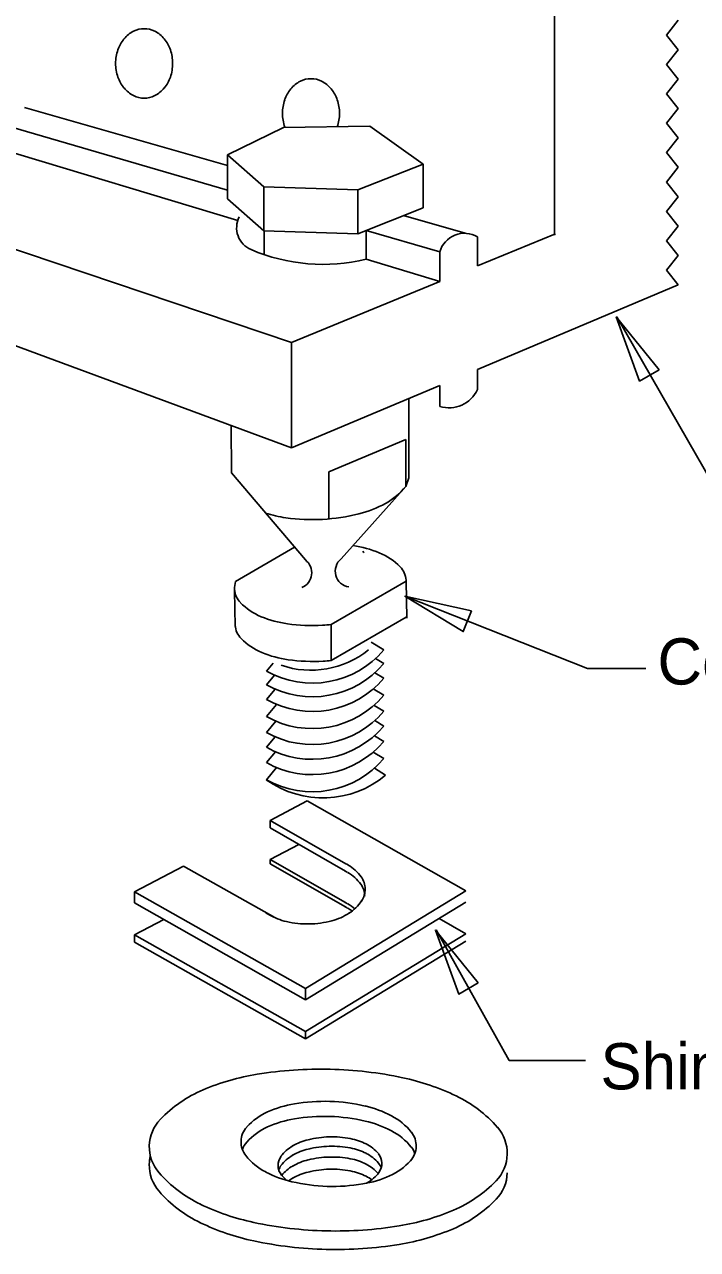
# Model space of a CAD drawing. Extents: x 12.3 to 19.6, y 5.9 to 16.2.
# Drawn here: x 16.612 to 17.486, y 8.113 to 9.704 of the extents above; entities that cross this region are included whole.
import ezdxf

# ---------------------------------------------------------------- set-up
doc = ezdxf.new("R2010")
doc.units = 0
for name, color, linetype in [('DETL-DIMS', 7, 'Continuous'), ('DETL-LINE', 7, 'Continuous'), ('DETL-NOTE', 7, 'Continuous')]:
    doc.layers.add(name, color=color, linetype=linetype)

msp = doc.modelspace()

# ---------------------------------------------------------------- linework, layer by layer
at = {"layer": 'DETL-DIMS'}
for p, q in [((17.5181, 9.086), (17.3812, 9.3241)), ((17.343, 8.8676), (17.1061, 8.9614)), ((17.343, 8.8676), (17.419, 8.8676)), ((17.2413, 8.3586), (17.1466, 8.5283)), ((17.2413, 8.3586), (17.3404, 8.3586))]:
    msp.add_line(p, q, dxfattribs=at)
for points in [[(17.4359, 9.2552), (17.4106, 9.2408), (17.3803, 9.324)], [(17.1925, 8.9426), (17.1817, 8.9156), (17.1061, 8.9614)], [(17.2013, 8.4594), (17.176, 8.445), (17.1457, 8.5281)]]:
    msp.add_lwpolyline(points, close=True, dxfattribs=at)
at = {"layer": 'DETL-LINE'}
for p, q in [((17.3004, 9.4304), (17.3004, 9.9587)), ((17.4456, 9.6901), (17.4606, 9.7092)), ((17.4606, 9.671), (17.4456, 9.6901)), ((17.4456, 9.6519), (17.4606, 9.671)), ((17.4456, 9.6519), (17.4606, 9.6328)), ((17.4456, 9.6138), (17.4606, 9.6328)), ((17.4606, 9.5947), (17.4456, 9.6138)), ((16.8756, 9.5208), (16.6122, 9.5959)), ((17.4456, 9.5756), (17.4606, 9.5947)), ((16.8756, 9.4888), (16.5709, 9.5777)), ((17.4606, 9.5565), (17.4456, 9.5756)), ((16.9485, 9.5698), (16.8756, 9.5344)), ((17.0607, 9.5718), (16.9485, 9.5698)), ((17.1296, 9.5226), (17.0607, 9.5718)), ((16.9588, 9.291), (16.1845, 9.552)), ((16.8892, 9.4491), (16.5709, 9.545)), ((17.4456, 9.5374), (17.4606, 9.5565)), ((16.8756, 9.4773), (16.8756, 9.5344)), ((16.8756, 9.5344), (16.9229, 9.4931)), ((17.4606, 9.5183), (17.4456, 9.5374)), ((17.0449, 9.4891), (17.1296, 9.5226)), ((17.1296, 9.4655), (17.1296, 9.5226)), ((17.4456, 9.4992), (17.4606, 9.5183)), ((17.4606, 9.4802), (17.4456, 9.4992)), ((16.9229, 9.4931), (17.0449, 9.4891)), ((16.9229, 9.436), (16.9229, 9.4931)), ((17.0449, 9.4321), (17.0449, 9.4891)), ((17.4456, 9.4611), (17.4606, 9.4802)), ((16.8756, 9.4773), (16.9229, 9.436)), ((17.0449, 9.4321), (17.1296, 9.4655)), ((17.1843, 9.4328), (17.1043, 9.4556)), ((17.4606, 9.442), (17.4456, 9.4611)), ((16.9588, 9.154), (16.1845, 9.4402)), ((16.9229, 9.436), (17.0449, 9.4321)), ((16.9235, 9.405), (16.9235, 9.436)), ((17.0557, 9.4363), (17.0557, 9.399)), ((17.1512, 9.4085), (17.0557, 9.4363)), ((17.2004, 9.3905), (17.3016, 9.4321)), ((17.4456, 9.4229), (17.4606, 9.442)), ((17.2004, 9.4282), (17.2004, 9.3905)), ((17.4606, 9.4038), (17.4456, 9.4229)), ((17.1512, 9.4085), (17.1512, 9.3702)), ((17.4456, 9.3847), (17.4606, 9.4038)), ((17.1512, 9.3702), (17.0557, 9.399)), ((17.4606, 9.3656), (17.4456, 9.3847)), ((16.9588, 9.291), (17.1512, 9.3702)), ((17.4606, 9.3656), (17.2004, 9.2559)), ((16.9588, 9.154), (16.9588, 9.291)), ((17.2004, 9.2559), (17.2004, 9.2297)), ((17.1512, 9.2351), (16.9588, 9.154)), ((17.1512, 9.2351), (17.1512, 9.2077)), ((17.1111, 9.1152), (17.1111, 9.2182)), ((16.8805, 9.183), (16.881, 9.1215)), ((17.0074, 9.1228), (17.1071, 9.1649)), ((17.1071, 9.1041), (17.1071, 9.165)), ((16.881, 9.1215), (16.9768, 9.0085)), ((17.0074, 9.1228), (17.0074, 9.0619)), ((17.1071, 9.104), (17.1111, 9.1152)), ((17.1071, 9.104), (17.0232, 9.01)), ((16.8863, 8.9806), (16.9627, 9.025)), ((16.9722, 8.9727), (16.9722, 8.9727)), ((17.0105, 8.9247), (17.1075, 8.9811)), ((17.1075, 8.9811), (17.1084, 8.933)), ((16.8849, 8.969), (16.8858, 8.9223)), ((17.0105, 8.878), (17.1075, 8.9344)), ((17.0105, 8.878), (17.0105, 8.9247)), ((17.0787, 8.8918), (17.0621, 8.9018)), ((16.935, 8.8747), (16.9262, 8.8642)), ((17.0787, 8.8742), (17.068, 8.8806)), ((16.9366, 8.859), (16.9262, 8.8466)), ((17.0787, 8.855), (17.067, 8.8621)), ((16.9375, 8.8409), (16.9262, 8.8274)), ((17.0787, 8.8328), (17.0649, 8.8411)), ((16.9394, 8.821), (16.9262, 8.8052)), ((17.0787, 8.8121), (17.066, 8.8198)), ((16.9385, 8.7991), (16.9262, 8.7845)), ((17.0787, 8.7929), (17.067, 8.8)), ((17.0787, 8.773), (17.0665, 8.7804)), ((16.9375, 8.7789), (16.9262, 8.7654)), ((16.938, 8.7595), (16.9262, 8.7454)), ((17.0787, 8.7508), (17.0649, 8.7591)), ((16.9394, 8.739), (16.9262, 8.7232)), ((17.081, 8.7293), (17.0664, 8.7381)), ((16.9791, 8.6957), (16.9312, 8.6705)), ((17.1852, 8.579), (16.9791, 8.6957)), ((17.0292, 8.6142), (16.9312, 8.6705)), ((16.9312, 8.6705), (16.9312, 8.6606)), ((17.0287, 8.6046), (16.9312, 8.6606)), ((16.9682, 8.6393), (16.9312, 8.6198)), ((16.8186, 8.6112), (16.755, 8.5778)), ((16.937, 8.5442), (16.8186, 8.6112)), ((17.0287, 8.5639), (16.9312, 8.6198)), ((16.9312, 8.6198), (16.9312, 8.6142)), ((17.0287, 8.5582), (16.9312, 8.6142)), ((16.9769, 8.4521), (16.755, 8.5778)), ((16.755, 8.5778), (16.755, 8.5632)), ((16.9769, 8.4521), (17.1852, 8.579)), ((16.9769, 8.4375), (16.755, 8.5632)), ((16.9769, 8.4375), (17.1852, 8.5644)), ((16.7929, 8.5417), (16.755, 8.5218)), ((17.1852, 8.523), (17.1504, 8.5432)), ((16.9769, 8.3962), (16.755, 8.5218)), ((16.755, 8.5218), (16.755, 8.5125)), ((16.9769, 8.3868), (16.755, 8.5125)), ((16.9769, 8.3962), (17.1852, 8.523)), ((16.9769, 8.3868), (17.1852, 8.5137)), ((16.9769, 8.4521), (16.9769, 8.4375)), ((16.9769, 8.3962), (16.9769, 8.3868))]:
    msp.add_line(p, q, dxfattribs=at)
for centre, radius, start, end in [((16.7711, 9.6607), 0.0384, 116.7848, 140.6296), ((16.7675, 9.6677), 0.0306, 90, 116.7848), ((16.7675, 9.6677), 0.0306, 63.2152, 90), ((16.764, 9.6607), 0.0384, 39.3704, 63.2152), ((16.7853, 9.6532), 0.0548, 161.2281, 180), ((16.7766, 9.6562), 0.0456, 140.6296, 161.2281), ((16.7584, 9.6562), 0.0456, 18.7719, 39.3704), ((16.7497, 9.6532), 0.0548, 0, 18.7719), ((16.7853, 9.6532), 0.0548, 180, 198.7719), ((16.7497, 9.6532), 0.0548, 341.2281, 360), ((16.7766, 9.6502), 0.0456, 198.7719, 219.3704), ((16.7584, 9.6502), 0.0456, 320.6296, 341.2281), ((16.9876, 9.5958), 0.0384, 116.7848, 140.6296), ((16.9841, 9.6028), 0.0306, 90, 116.7848), ((16.9841, 9.6028), 0.0306, 63.2152, 90), ((16.9805, 9.5958), 0.0384, 39.3704, 63.2152), ((16.7711, 9.6457), 0.0384, 219.3704, 243.2152), ((16.7675, 9.6387), 0.0306, 243.2152, 270), ((16.7675, 9.6387), 0.0306, 270, 296.7848), ((16.764, 9.6457), 0.0384, 296.7848, 320.6296), ((16.9931, 9.5912), 0.0456, 140.6296, 161.2281), ((16.975, 9.5912), 0.0456, 18.7719, 39.3704), ((17.0019, 9.5883), 0.0548, 161.2281, 180), ((16.9663, 9.5883), 0.0548, 0, 18.7719), ((17.0019, 9.5883), 0.0548, 180, 198.7719), ((16.9663, 9.5883), 0.0548, 341.6289, 360), ((16.9931, 9.5853), 0.0456, 198.7719, 199.8757), ((16.9182, 9.4397), 0.0306, 152.4295, 247.0577), ((17.1834, 9.3992), 0.0335, 59.5806, 163.9975), ((16.9999, 9.6303), 0.238, 246.8407, 283.5448), ((17.163, 9.2474), 0.0413, 253.4056, 334.7721), ((17.0409, 9.156), 0.0841, 298.4051, 321.8735), ((17.085, 9.1213), 0.0281, 321.8735, 321.9986), ((17.0095, 9.2141), 0.1502, 284.1911, 298.4051), ((16.9723, 9.2121), 0.1502, 251.6999, 262.0493), ((16.9857, 9.308), 0.2471, 273.1202, 284.1911), ((16.9857, 9.308), 0.2471, 262.0493, 273.1202), ((17.0061, 8.794), 0.2354, 82.0493, 82.0908), ((17.0188, 8.8854), 0.1431, 67.8353, 82.0493), ((17.0312, 9.0003), 0.0281, 38.0014, 44.3669), ((17.0426, 8.9436), 0.0801, 44.3669, 67.8353), ((16.9643, 8.9919), 0.0208, 292.4347, 53.0065), ((17.0363, 8.9939), 0.0207, 129.1655, 261.1608), ((17.0808, 8.981), 0.0267, 3.1202, 44.3669), ((16.9115, 8.9718), 0.0267, 160.5994, 183.1202), ((16.9115, 8.9718), 0.0267, 183.1202, 224.3669), ((17.0808, 8.981), 0.0267, 0.1573, 3.1202), ((16.9497, 9.0091), 0.0801, 224.3669, 247.8353), ((16.9124, 8.9252), 0.0267, 176.2002, 183.1202), ((16.9124, 8.9252), 0.0267, 183.1202, 224.3669), ((16.9734, 9.0674), 0.1431, 247.8353, 262.0493), ((16.9862, 9.1588), 0.2354, 262.0493, 273.1202), ((16.9862, 9.1588), 0.2354, 273.1202, 275.9189), ((16.9506, 8.9625), 0.0801, 224.3669, 247.8353), ((16.9858, 8.9701), 0.1215, 240.5948, 319.9009), ((16.9839, 8.985), 0.1196, 251.153, 308.7624), ((16.9743, 9.0208), 0.1431, 247.8353, 262.0493), ((16.9871, 9.1122), 0.2354, 262.0493, 273.1202), ((16.9871, 9.1122), 0.2354, 273.1202, 275.6963), ((16.9858, 8.9524), 0.1215, 240.5948, 319.9009), ((16.9858, 8.9333), 0.1215, 240.5948, 319.9009), ((16.9858, 8.9111), 0.1215, 240.5948, 319.9009), ((16.9858, 8.8904), 0.1215, 240.5948, 319.9009), ((16.9858, 8.8712), 0.1215, 240.5948, 319.9009), ((16.9858, 8.8513), 0.1215, 240.5948, 319.9009), ((16.9858, 8.8291), 0.1215, 240.5948, 319.9009), ((16.9996, 8.8262), 0.1266, 234.4998, 310.0333), ((16.9906, 8.5319), 0.082, 59.8969, 62.3546), ((16.9912, 8.5416), 0.082, 59.8969, 62.3546), ((17.0052, 8.5657), 0.0541, 35.47, 59.8969), ((17.0046, 8.5561), 0.0541, 35.47, 59.8969), ((17.0267, 8.581), 0.0277, 1.041, 35.47), ((17.0262, 8.5714), 0.0277, 1.041, 35.47), ((17.0267, 8.581), 0.0277, 326.6119, 1.041), ((16.9906, 8.4912), 0.082, 59.8969, 62.3546), ((16.9906, 8.4856), 0.082, 59.8969, 62.3546), ((17.0046, 8.5153), 0.0541, 47.853, 59.8969), ((17.0046, 8.5097), 0.0541, 52.5346, 59.8969), ((17.0046, 8.5956), 0.0541, 302.185, 326.6119), ((16.9568, 8.5947), 0.0541, 234.1623, 239.8969), ((16.9708, 8.6189), 0.082, 239.8969, 256.9883), ((16.9898, 8.6192), 0.082, 285.0936, 302.185), ((16.9796, 8.6569), 0.121, 256.9883, 271.041), ((16.9796, 8.6569), 0.121, 271.041, 285.0936), ((16.9637, 8.0376), 0.3072, 99.2321, 112.9408), ((16.9968, 7.8342), 0.5133, 88.6369, 99.2321), ((16.9968, 7.8342), 0.5133, 78.0417, 88.6369), ((17.0395, 8.0358), 0.3072, 64.3331, 78.0417), ((16.9093, 8.1661), 0.1676, 112.9408, 136.1093), ((16.9864, 8.161), 0.1435, 99.5736, 114.0913), ((17.0014, 8.072), 0.2337, 88.2112, 99.5736), ((17.0014, 8.072), 0.2337, 76.8488, 88.2112), ((17.1, 8.1616), 0.1676, 41.1645, 64.3331), ((16.9612, 8.2174), 0.0817, 114.0913, 137.7207), ((17.0014, 8.0525), 0.2337, 88.2112, 99.5736), ((17.0219, 8.1599), 0.1435, 62.3311, 76.8488), ((17.0506, 8.2146), 0.0817, 38.7017, 62.3311), ((16.8256, 8.2467), 0.0514, 136.1093, 178.6369), ((16.9219, 8.2531), 0.0286, 137.7207, 178.2112), ((16.9612, 8.1979), 0.0817, 114.0913, 137.7207), ((16.9864, 8.1415), 0.1435, 99.5736, 114.0913), ((17.0014, 8.0525), 0.2337, 76.8488, 88.2112), ((17.0219, 8.1403), 0.1435, 62.3311, 76.8488), ((17.1875, 8.2381), 0.0514, 358.6369, 41.1645), ((17, 8.1773), 0.0809, 103.8602, 119.3743), ((17.0112, 8.1323), 0.1273, 91.5065, 103.8602), ((17.0112, 8.1323), 0.1273, 79.1528, 91.5065), ((17.0199, 8.1778), 0.0809, 63.6387, 79.1528), ((17.0506, 8.1951), 0.0817, 38.7017, 62.3311), ((17.0921, 8.2478), 0.0286, 358.2112, 38.7017), ((16.8256, 8.2467), 0.0514, 178.6369, 221.1645), ((16.9219, 8.2531), 0.0286, 178.2112, 218.7017), ((16.9219, 8.2336), 0.0286, 137.7207, 160.0349), ((16.9842, 8.2054), 0.0486, 119.3743, 143.4322), ((17, 8.1652), 0.0809, 103.8602, 119.3743), ((17.0112, 8.1201), 0.1273, 91.5065, 103.8602), ((17.0112, 8.1201), 0.1273, 79.1528, 91.5065), ((17.0199, 8.1657), 0.0809, 63.6387, 79.1528), ((17.0342, 8.2068), 0.0486, 39.5808, 63.6387), ((17.0921, 8.2478), 0.0286, 317.7207, 358.2112), ((17.0921, 8.2283), 0.0286, 19.9651, 38.7017), ((16.8256, 8.2227), 0.0514, 166.4892, 178.6369), ((16.8256, 8.2227), 0.0514, 178.6369, 221.1645), ((16.9633, 8.2863), 0.0817, 218.7017, 242.3311), ((16.9611, 8.2226), 0.0198, 143.4322, 181.5065), ((16.9842, 8.1933), 0.0486, 119.3743, 143.4322), ((17, 8.1512), 0.0809, 103.8602, 119.3743), ((17.0112, 8.1061), 0.1273, 91.5065, 103.8602), ((17.0112, 8.1061), 0.1273, 79.1528, 91.5065), ((17.0199, 8.1517), 0.0809, 63.6387, 79.1528), ((17.0342, 8.1946), 0.0486, 39.5808, 63.6387), ((17.0342, 8.1806), 0.0486, 40.205, 63.6387), ((17.0564, 8.2251), 0.0198, 1.5065, 39.5808), ((17.0564, 8.2129), 0.0198, 17.8482, 39.5808), ((17.0564, 8.2251), 0.0198, 323.4322, 1.5065), ((17.0528, 8.2835), 0.0817, 294.0913, 317.7207), ((17.1875, 8.2381), 0.0514, 316.1093, 358.6369), ((16.9131, 8.3232), 0.1676, 221.1645, 244.3331), ((16.992, 8.341), 0.1435, 242.3311, 256.8488), ((16.9611, 8.2226), 0.0198, 181.5065, 219.5808), ((16.9611, 8.2104), 0.0198, 143.4322, 162.1518), ((16.9833, 8.2409), 0.0486, 219.5808, 231.184), ((16.9842, 8.1793), 0.0486, 119.3743, 141.5294), ((17, 8.1353), 0.0809, 103.8602, 119.3743), ((17.0112, 8.0903), 0.1273, 91.5065, 103.8602), ((17.0112, 8.0903), 0.1273, 79.1528, 91.5065), ((17.0199, 8.1359), 0.0809, 63.6387, 79.1528), ((17.0276, 8.3399), 0.1435, 279.5736, 294.0913), ((17.0342, 8.1648), 0.0486, 53.4904, 63.6387), ((17.0333, 8.2422), 0.0486, 299.3743, 323.4322), ((17.1875, 8.2141), 0.0514, 316.1093, 358.6369), ((16.9842, 8.1635), 0.0486, 119.3743, 126.7911), ((17.0125, 8.4289), 0.2337, 256.8488, 268.2112), ((17.0125, 8.4289), 0.2337, 268.2112, 279.5736), ((17.0175, 8.2703), 0.0809, 298.6321, 299.3743), ((17.1037, 8.3187), 0.1676, 292.9408, 316.1093), ((16.9131, 8.2992), 0.1676, 221.1645, 244.3331), ((17.1037, 8.2947), 0.1676, 292.9408, 316.1093), ((16.9735, 8.449), 0.3072, 244.3331, 258.0417), ((17.0493, 8.4472), 0.3072, 279.2321, 292.9408), ((16.9735, 8.425), 0.3072, 244.3331, 258.0417), ((17.0162, 8.6506), 0.5133, 258.0417, 268.6369), ((17.0162, 8.6506), 0.5133, 268.6369, 279.2321), ((17.0493, 8.4232), 0.3072, 279.2321, 292.9408), ((17.0162, 8.6266), 0.5133, 258.0417, 268.6369), ((17.0162, 8.6266), 0.5133, 268.6369, 279.2321)]:
    msp.add_arc(centre, radius, start, end, dxfattribs=at)

# ---------------------------------------------------------------- texts
at = {"layer": 'DETL-NOTE'}
for s, p in [('Coupling', (17.4339, 8.8468)), ('Shims', (17.3599, 8.3212))]:
    msp.add_text(s, height=0.06, dxfattribs=at).set_placement(p)

doc.saveas('drawing.dxf')
